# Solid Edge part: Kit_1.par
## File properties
Last saved by: bmolnar
Revision: 76
Dokumentum tartalom típus: 0
Sűrűség: 0,000 kg/m^3
Pontosság: 0,990
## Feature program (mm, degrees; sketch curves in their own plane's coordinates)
base feature "unnamed BaseFeature 1"
thread "unnamed Thread 1"
sketch for "unnamed Hole 1" plane through (-23.25, -23.25, 90) normal (0, 0, 1) x-axis (0, 1, 0)
  hole centre (0, 0) bore radius 3.3235
hole "unnamed Hole 1" through
sketch for "unnamed Hole 2" plane through (-23.25, -23.25, 90) normal (0, 0, 1) x-axis (0, 1, 0)
  hole centre (46.5, 0) bore radius 3.3235
hole "unnamed Hole 2" through
sketch for "unnamed Hole 3" plane through (-23.25, -23.25, 90) normal (0, 0, 1) x-axis (0, 1, 0)
  hole centre (0, -46.5) bore radius 3.3235
hole "unnamed Hole 3" through
sketch for "unnamed Hole 4" plane through (-23.25, -23.25, 90) normal (0, 0, 1) x-axis (0, 1, 0)
  hole centre (46.5, -46.5) bore radius 3.3235
hole "unnamed Hole 4" through
pattern "unnamed Pattern 1" of "unnamed Hole 1", "unnamed Hole 2", "unnamed Hole 3", "unnamed Hole 4"
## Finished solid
Body 1: solid body, 320 faces, 747 edges, 446 vertices, 4 internal voids.
  Faces by surface: plane 141, cylinder 83, swept 53, torus 22, cone 20, spline 1
  Edges by curve: line 413, circle 177, spline 118, ellipse 28, curve on surface 10, intersection 1
Bounding box of the edges (mm; curved faces can reach further): 65.500 x 65.500 x 14.500, from (-32.75, -32.75, 80.5) to (32.75, 32.75, 95).
Cylindrical faces by radius (mm): R0.2 x40, R0.201 x2, R0.2012 x2, R1.75 x1, R2.5402 x12, R2.6 x4, R3.3235 x4, R3.75 x4, R3.85 x4, R4.283 x1, R5.25 x4, R8.27 x1, R8.85 x1, R9 x1, R10.25 x1, R15.5811 x1
Conical faces (half-angle, radius in mm at the cone's reference point): 0.5 deg R6.5 x2, 0.5 deg R8 x4, 7 deg R9.5925 x1, 14 deg R8.135 x1, 14 deg R8.4811 x1, 17 deg R8.135 x1, 23 deg R8.829 x1, 42.5 deg R8.1233 x1, 45 deg R3.6735 x4, 45 deg R9 x1, 84 deg R8.4608 x1, 85 deg R9.9463 x1, 87 deg R8.1765 x1
Toroidal faces (ring radius, tube radius in mm): R2.9402 r0.4 x12, R3.55 r0.2 x8, R8.8057 r0.2025 x1, R9.2522 r0.2925 x1
Planar faces by outward normal: +x 12, +y 12, +z 24, -x 14, -y 12, -z 1, oblique 66
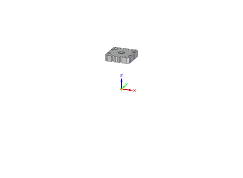
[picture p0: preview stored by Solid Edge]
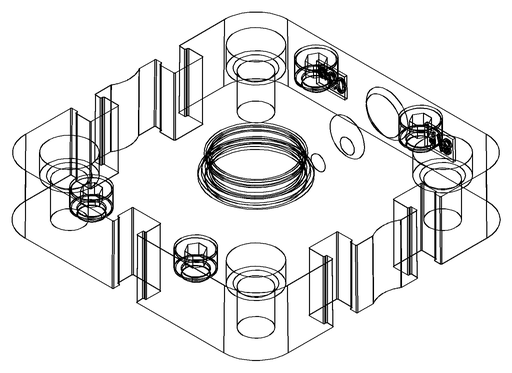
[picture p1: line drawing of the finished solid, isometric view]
